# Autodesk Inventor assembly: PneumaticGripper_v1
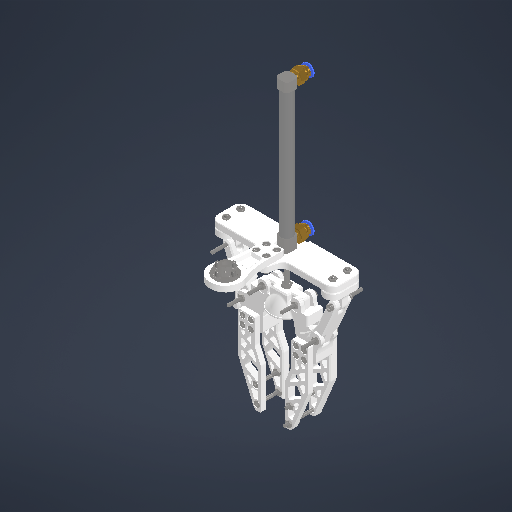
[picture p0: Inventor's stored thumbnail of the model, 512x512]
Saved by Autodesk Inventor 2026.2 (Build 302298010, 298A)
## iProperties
Created: 2026-05
Part Number: PneumaticGripper_v1
Document SubType Name: Assembly
Designer: work
Author: work
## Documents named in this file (16)
- C:\Users\work\Desktop\ARD_v1\ARD_hardware\PneumaticGripper_v1\PneumaticGripper_v1.iam
- C:\Users\work\Desktop\ARD_v1\ARD_hardware\PneumaticGripper_v1\Pneumatic fitting\CDJ2B10_100\CDJ2B10.iam
- C:\Users\work\Desktop\ARD_v1\ARD_hardware\PneumaticGripper_v1\Cylinder fixing parts.ipt
- C:\Users\work\Desktop\ARD_v1\ARD_hardware\PneumaticGripper_v1\rod-fixing parts.ipt
- C:\Users\work\Desktop\ARD_v1\ARD_hardware\PneumaticGripper_v1\Pneumatic fitting\CDJ2B10_100\Rod.ipt
- C:\Users\work\Desktop\ARD_v1\ARD_hardware\PneumaticGripper_v1\Pneumatic fitting\CDJ2B10_100\AS 1474 - M4(1).ipt
- C:\Users\work\Desktop\ARD_v1\ARD_hardware\PneumaticGripper_v1\Bottom Link Parts.ipt
- C:\Users\work\Desktop\ARD_v1\ARD_hardware\PneumaticGripper_v1\Link Support Parts.ipt
- C:\Users\work\Desktop\ARD_v1\ARD_hardware\PneumaticGripper_v1\Link Parts.ipt
- C:\Users\work\Desktop\ARD_v1\ARD_hardware\PneumaticGripper_v1\Tongs_R.ipt
- C:\Users\work\Desktop\ARD_v1\ARD_hardware\PneumaticGripper_v1\Tongs_l.ipt
- C:\Users\work\Desktop\ARD_v1\ARD_hardware\SCARA_v1\Object\KS B 1003 - M 3 x 12.ipt
- C:\Users\work\Desktop\ARD_v1\ARD_hardware\PneumaticGripper_v1\Object\KS B 1003 - M 3 x 30.ipt
- C:\Users\work\Desktop\ARD_v1\ARD_hardware\PneumaticGripper_v1\Object\JIS B 1181 - A_B M3.ipt
- C:\Users\work\Desktop\ARD_v1\ARD_hardware\PneumaticGripper_v1\Flange Bracket.ipt
- C:\Users\work\Desktop\ARD_v1\ARD_hardware\PneumaticGripper_v1\Object\flange joint 16pi (5 to 3).ipt
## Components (81 placed, 15 different names)
1. CDJ2B10:1 [sub-assembly] — 각도:1
2. Cylinder fixing parts:1
3. rod-fixing parts:1
4. Rod:1 — 플러쉬:1
5. Flange Bracket:1
6. AS 1474 - M4(1):1 — 각도:2, 플러쉬:1
7. AS 1474 - M4(1):2 — 각도:3
8. Bottom Link Parts:1
9. Bottom Link Parts:2
10. Link Support Parts:1
11. Link Support Parts:2
12. Link Parts:1
13. Link Parts:3
14. Tongs_R:1
15. Tongs_l:1
16. Tongs_R:3
17. Tongs_l:2
18. JIS B 1181 - A_B M3:18
19. JIS B 1181 - A_B M3:19
20. JIS B 1181 - A_B M3:20
21. JIS B 1181 - A_B M3:21
22. JIS B 1181 - A_B M3:22
23. JIS B 1181 - A_B M3:23
24. JIS B 1181 - A_B M3:24
25. JIS B 1181 - A_B M3:25
26. KS B 1003 - M 3 x 12:22
27. KS B 1003 - M 3 x 12:23
28. KS B 1003 - M 3 x 12:24
29. KS B 1003 - M 3 x 12:25
30. KS B 1003 - M 3 x 12:26
31. KS B 1003 - M 3 x 12:27
32. KS B 1003 - M 3 x 12:28
33. KS B 1003 - M 3 x 12:29
34. KS B 1003 - M 3 x 12:1
35. KS B 1003 - M 3 x 12:2
36. KS B 1003 - M 3 x 12:3
37. KS B 1003 - M 3 x 12:4
38. KS B 1003 - M 3 x 12:5
39. KS B 1003 - M 3 x 12:6
40. KS B 1003 - M 3 x 12:7
41. KS B 1003 - M 3 x 12:8
42. KS B 1003 - M 3 x 12:9
43. KS B 1003 - M 3 x 12:11
44. KS B 1003 - M 3 x 12:12
45. KS B 1003 - M 3 x 12:13
46. KS B 1003 - M 3 x 12:14
47. KS B 1003 - M 3 x 12:15
48. KS B 1003 - M 3 x 12:16
49. KS B 1003 - M 3 x 12:17
50. KS B 1003 - M 3 x 12:18
51. KS B 1003 - M 3 x 12:19
52. KS B 1003 - M 3 x 12:20
53. KS B 1003 - M 3 x 12:21
54. KS B 1003 - M 3 x 30:1
55. KS B 1003 - M 3 x 30:2
56. KS B 1003 - M 3 x 30:3
57. flange joint 16pi (5 to 3):1
58. KS B 1003 - M 3 x 30:4
59. KS B 1003 - M 3 x 30:5
60. KS B 1003 - M 3 x 30:6
61. KS B 1003 - M 3 x 30:7
62. KS B 1003 - M 3 x 30:8
63. KS B 1003 - M 3 x 30:9
64. KS B 1003 - M 3 x 30:10
65. JIS B 1181 - A_B M3:1
66. JIS B 1181 - A_B M3:2
67. JIS B 1181 - A_B M3:3
68. JIS B 1181 - A_B M3:4
69. JIS B 1181 - A_B M3:5
70. JIS B 1181 - A_B M3:6
71. JIS B 1181 - A_B M3:7
72. JIS B 1181 - A_B M3:8
73. JIS B 1181 - A_B M3:9
74. JIS B 1181 - A_B M3:10
75. JIS B 1181 - A_B M3:11
76. JIS B 1181 - A_B M3:12
77. JIS B 1181 - A_B M3:13
78. JIS B 1181 - A_B M3:14
79. JIS B 1181 - A_B M3:15
80. JIS B 1181 - A_B M3:16
81. JIS B 1181 - A_B M3:17
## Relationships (4: Angle 3, Flush 1)
- 각도:1 [Angle]: CDJ2B10:1
- 각도:2 [Angle]: AS 1474 - M4(1):1
- 각도:3 [Angle]: AS 1474 - M4(1):2
- 플러쉬:1 [Flush]: Rod:1 ↔ AS 1474 - M4(1):1
